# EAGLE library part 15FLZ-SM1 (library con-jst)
CONNECTOR
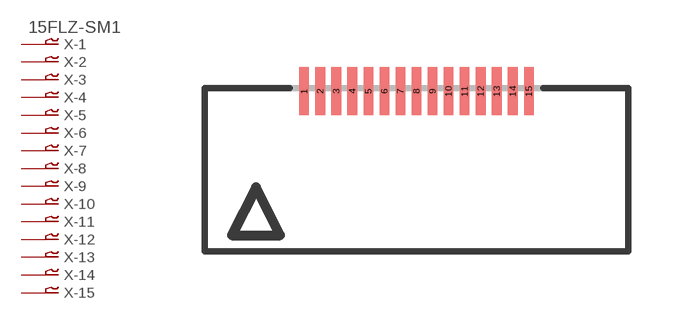
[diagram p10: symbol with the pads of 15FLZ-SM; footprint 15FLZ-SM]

Designator prefix X; gates -1=P-VN -2=P-N -3=P-N -4=P-N -5=P-N -6=P-N -7=P-N -8=P-N -9=P-N -10=P-N -11=P-N -12=P-N -13=P-N -14=P-N -15=P-N

## 15FLZ-SM1 (OC_FARNELL: unknown; OC_NEWARK: unknown)  [15FLZ-SM]
1  -1:1  pas
2  -2:1  pas
3  -3:1  pas
4  -4:1  pas
5  -5:1  pas
6  -6:1  pas
7  -7:1  pas
8  -8:1  pas
9  -9:1  pas
10  -10:1  pas
11  -11:1  pas
12  -12:1  pas
13  -13:1  pas
14  -14:1  pas
15  -15:1  pas

## Footprint 15FLZ-SM (pad centres in mm)
CONNECTOR
smd 0.3 x 1.5: 1 -3.5,2.5; 2 -3,2.5; 3 -2.5,2.5; 4 -2,2.5; 5 -1.5,2.5; 6 -1,2.5; 7 -0.5,2.5; 8 0,2.5; 9 0.5,2.5; 10 1,2.5; 11 1.5,2.5; 12 2,2.5; 13 2.5,2.5; 14 3,2.5; 15 3.5,2.5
